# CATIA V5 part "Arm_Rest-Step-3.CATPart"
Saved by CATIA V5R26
Part number: Arm_Rest
Bounding box of the stored display mesh (mm): x 743.798 to 1432.298, y -782.976 to -630.25, z 345.981 to 534.311
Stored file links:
  D:\LinkedIn Learning\NURBS\CATIA\Class Parts\Arm_Rest-Step-3.CATPart
  D:\LinkedIn Learning\NURBS\Arm_Rest.CATPart
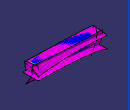
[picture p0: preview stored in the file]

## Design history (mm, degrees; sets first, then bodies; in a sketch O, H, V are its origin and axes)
AxisSystem1: origin (0, 0, 0), X (1, 0, 0), Y (0, 1, 0), Z (0, 0, 1)
StDynAnalysisRootNodeFeature1 "CATStDynAnalysisRootNodeName"
Set1 "REF DATA"
  CLDGeom1 "TOP"
  CLDGeom2 "FRONT"
  CLDGeom3 "AFT_BLEND"
  CLDGeom4 "END_AFT"
  CLDGeom5 "FORWARD_BLEND"
  CLDGeom6 "BOTTOM"
  CLDGeom7 "END_FORWARD"
  CLDGeom8 "UPPER_BLENDS"
  CLDGeom9 "LOWER_BLENDS"
  DatumSurface1 "DOOR_TRIM_SURFACE"
Set2 "FORM"
  Set3 "SLABS"
    DatumSurface2 to DatumSurface6
Body1 (main body)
